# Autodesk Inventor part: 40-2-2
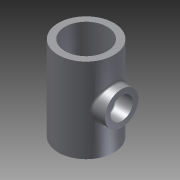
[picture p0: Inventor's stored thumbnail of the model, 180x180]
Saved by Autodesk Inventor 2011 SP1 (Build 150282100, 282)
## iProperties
Created: 2014-01
Part Number: 40-2-2
Document SubType Name: Modeling
Designer: Administrator
Density: 1 g/cm^3
Author: Administrator
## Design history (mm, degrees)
sketch "草图1"
  geometry: C1 r 12.5 at (0, 0); 1 further point
  constraints: 1 centre point, 1 coincident
  dimensions: "d0" = 25 diameter of C1
extrude "拉伸1" new body sketch "草图1" distance "d1" = 38; taper "d2" = 0 deg
hole "Hole1" diameter "d5" = 19; stored, may be unused: countersink angle "d9" = 90 deg, drill point angle "d11" = 118 deg; dims "d3" = 10, "d4" = 10, "d6" = 6, "d7" = 4, "d8" = 2, "d10" = 8
node "工作平面1"
sketch "草图2"
  geometry: L1 (12.5, 0)-(12.5, 38) reference; C1 r 7.5 at (0, 19); 2 further points
  constraints: 1 centre point, 1 horizontal alignment, 1 midpoint
  dimensions: "d13" = 15 diameter of C1
extrude "拉伸2" join sketch "草图2" stored distance "d14" = 38; taper "d15" = 0 deg
hole "Hole2" diameter "d18" = 10; stored, may be unused: countersink angle "d22" = 90 deg, drill point angle "d24" = 118 deg; dims "d16" = 10, "d17" = 10, "d19" = 6, "d20" = 4, "d21" = 2, "d23" = 10
fillet "圆角1" dims "d25" = 1
node "实体1"
other parameters: "d12" = 16
